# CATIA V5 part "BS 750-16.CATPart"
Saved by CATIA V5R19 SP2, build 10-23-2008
Part number: BS 750-16
Bounding box of the stored display mesh (mm): x -22.494 to 22.494, y -22.494 to 22.494, z 0 to 64
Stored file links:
  C:\Users\Bora\Desktop\3D Katı model\BS serisi\BS 750\BS 750-16.CATPart
  C:\Program Files\Dassault Systemes\B19\intel_a\reffiles\standard\MetricThickPitch.txt
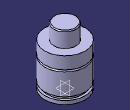
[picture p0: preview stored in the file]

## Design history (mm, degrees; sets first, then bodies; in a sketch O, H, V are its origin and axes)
Body1 (main body)
  Sketch1 on yz-plane, origin (0, 0, 0), H (0, 1, 0), V (0, 0, 1)
    point P3 (12.5, 63)
    point P5 (12.5, 63)
    point P7 (22.5, 33.5)
    point P8 (22.5, 31.5)
    point P12 (22.5, 31.5)
    point P13 (22.5, 33.5)
    line L1 (22.5, 0) -> (22.5, 4)
    line L2 (12.5, 63) -> (12.5, 47)
    arc A1 centre (11.5, 63) radius 1 from (12.5, 63) to (11.5, 64) ccw
    arc A2 centre (22.5, 32.5) radius 1 from (22.5, 33.5) to (22.5, 31.5) ccw
    line L3 (20, 7.5) -> (20, 4)
    line L4 (22.5, 7.5) -> (22.5, 31.5)
    line L5 (22.5, 33.5) -> (22.5, 47)
    line L6 (11.5, 64) -> (0, 64)
    point P15 (0, 64)
    line L7 (12.5, 47) -> (22.5, 47)
    line L8 (0, 0) -> (22.5, 0)
    line L9 (20, 7.5) -> (22.5, 7.5)
    line L10 (20, 4) -> (22.5, 4)
    coincidence: P15 V, P3 P5, P7 P13, P8 P12
    tangency: L6 A1
    horizontal: L7 H, L8 H, L9 H, L10 H
  Shaft1: profile Sketch1, axis Sketch1.V, angle 360
  Sketch2 on face of Shaft1 from Sketch1.L8, origin (0, 0, 0), H (1, 0, 0), V (0, -1, 0)
    point P1 (10, 0)
    distance P1 V = 10
  Hole1: placed by Sketch2, at (10, 0, 0) direction (0, 0, 1), diameter 6.647, depth 4, threaded "M8", thread diameter 8, thread depth 4, pitch 1.25
  CircPattern1: of Hole1, instances 2, angular step 180, axis from xy-plane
